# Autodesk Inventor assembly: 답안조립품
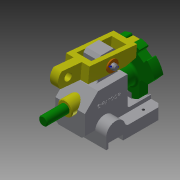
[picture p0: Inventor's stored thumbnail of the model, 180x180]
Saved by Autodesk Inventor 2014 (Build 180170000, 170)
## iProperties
Created: 2016-11
Part Number: 답안조립품
Document SubType Name: Assembly
Designer: USER
Author: USER
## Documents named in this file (8)
- C:\Users\USER\Desktop\461108V1019\답안조립품.iam
- C:\Users\USER\Desktop\461108V1019\본체.ipt
- C:\Users\USER\Desktop\461108V1019\부시.ipt
- C:\Users\USER\Desktop\461108V1019\분할대.ipt
- C:\Users\USER\Desktop\461108V1019\분할축.ipt
- C:\Users\USER\Desktop\461108V1019\와셔.ipt
- C:\Users\USER\Desktop\461108V1019\원통형핀.ipt
- C:\Users\USER\Desktop\461108V1019\클레비스핀.ipt
